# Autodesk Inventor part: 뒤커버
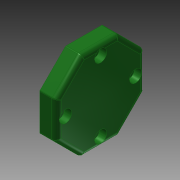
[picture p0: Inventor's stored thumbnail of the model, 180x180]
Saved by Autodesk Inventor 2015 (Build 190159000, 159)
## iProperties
Created: 2015-11
Part Number: 뒤커버
Material: 알루미늄 6061
Document SubType Name: Modeling
Designer: mduedu
Density: 1 g/cm^3
Appearance: 매끄러움 - 짙은 산림 녹색
Author: mduedu
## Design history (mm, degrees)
sketch "스케치5" dims "d66" = 58
  geometry: L1 (12.012, 29)-(29, 12.012); L2 (29, 12.012)-(29, -12.012); L3 (29, -12.012)-(12.012, -29); L4 (12.012, -29)-(-12.012, -29); L5 (-12.012, -29)-(-29, -12.012); L6 (-29, -12.012)-(-29, 12.012); L7 (-29, 12.012)-(-12.012, 29); L8 (-12.012, 29)-(12.012, 29); 4 further points
  constraints: 16 end point, 2 coincident, 2 vertical alignment, 1 midpoint, 19 other
extrude "돌출2" new body sketch "스케치5" distance "d67" = 11; taper "d68" = 0 deg
sketch "스케치6"
  geometry: C1 r 16 at (0, 0); 1 further point
  constraints: 1 centre point, 1 coincident
  dimensions: "d69" = 32 diameter of C1
extrude "돌출3" join sketch "스케치6" distance "d70" = 3; taper "d71" = 0 deg
hole "구멍5" diameter "d74" = 28; stored, may be unused: countersink angle "d78" = 90 deg, drill point angle "d80" = 0 deg; dims "d75" = 6, "d76" = 4, "d77" = 2, "d79" = 10, "d98" = 10, "d99" = 10
fillet "모깎기7" dims "d81" = 1
fillet "모깎기8" dims "d82" = 3
fillet "모깎기9" dims "d83" = 3
fillet "모깎기10" dims "d84" = 0.3
sketch "스케치7" dims "d85" = 46
  geometry: 3 further points
  constraints: 2 vertical alignment, 1 coincident, 2 other
hole "구멍6" sketch "스케치7" at (0, 23) diameter "d86" = 4.5; stored, may be unused: countersink angle "d90" = 90 deg, drill point angle "d92" = 0 deg; dims "d87" = 6, "d88" = 8, "d89" = 4.6, "d91" = 10
node "솔리드2"
pattern_circular "원형 패턴3" dims angle "d94" = 360 deg
